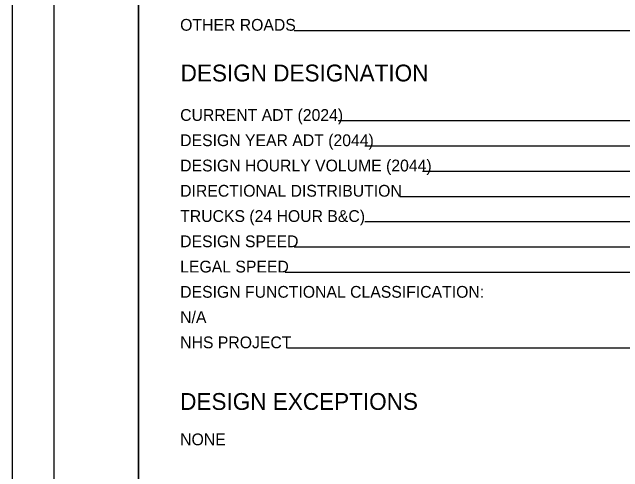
# Model space of a CAD drawing. Extents: x 0 to 34, y 0 to 22.
# Drawn here: x 0 to 7.25, y 5.64 to 11.1 of the extents above; entities that cross this region are included whole.
import ezdxf

# ---------------------------------------------------------------- set-up
doc = ezdxf.new("R2010")
doc.units = 0
for name, color, linetype in [('SH_Border', 7, 'Continuous'), ('SH_Cut_Line', 7, 'Continuous'), ('SH_Data', 7, 'Continuous'), ('SH_Text', 7, 'Continuous')]:
    doc.layers.add(name, color=color, linetype=linetype)

msp = doc.modelspace()

# ---------------------------------------------------------------- linework, layer by layer
at = {"layer": 'SH_Border'}
for points in [[(0.5, 21.5), (1.5, 21.5), (1.5, 0.5), (0.5, 0.5)], [(1.5, 21.5), (33.5, 21.5), (33.5, 0.5), (1.5, 0.5)]]:
    msp.add_lwpolyline(points, close=True, dxfattribs=at)
at = {"layer": 'SH_Cut_Line'}
msp.add_lwpolyline([(0, 0), (34, 0), (34, 22), (0, 22)], close=True, dxfattribs=at)
at = {"layer": 'SH_Data'}
for p, q in [((7.7, 10.8767), (3.3471, 10.8767)), ((7.6424, 9.8062), (3.871, 9.8062)), ((7.6368, 9.5062), (4.1885, 9.5062)), ((7.6368, 9.2062), (4.8723, 9.2062)), ((7.6368, 8.9062), (4.6037, 8.9062)), ((7.6368, 8.6062), (4.1885, 8.6062)), ((7.6368, 8.3062), (3.346, 8.3062)), ((7.6368, 8.0062), (3.2422, 8.0062)), ((7.6368, 7.1062), (3.2669, 7.1062))]:
    msp.add_line(p, q, dxfattribs=at)

# ---------------------------------------------------------------- texts
msp.add_text('DESIGN DESIGNATION', height=0.2, dxfattribs=at).set_placement((2, 10.2747))
at = {"layer": 'SH_Text'}
for s, height, p in [('OTHER ROADS', 0.14, (1.9944, 10.8767)), ('CURRENT ADT (2024)', 0.14, (1.9944, 9.8062)), ('DESIGN YEAR ADT (2044)', 0.14, (1.9944, 9.5062)), ('DESIGN HOURLY VOLUME (2044)', 0.14, (1.9944, 9.2062)), ('DIRECTIONAL DISTRIBUTION', 0.14, (1.9944, 8.9062)), ('TRUCKS (24 HOUR B&C)', 0.14, (1.9944, 8.6062)), ('DESIGN SPEED', 0.14, (1.9944, 8.3062)), ('LEGAL SPEED', 0.14, (1.9944, 8.0062)), ('DESIGN FUNCTIONAL CLASSIFICATION:', 0.14, (1.9944, 7.7062)), ('N/A', 0.14, (1.9944, 7.4062)), ('NHS PROJECT', 0.14, (1.9944, 7.1062)), ('DESIGN EXCEPTIONS', 0.2, (1.9944, 6.3744)), ('NONE', 0.14, (1.9944, 5.9544))]:
    msp.add_text(s, height=height, dxfattribs=at).set_placement(p)

doc.saveas('drawing.dxf')
